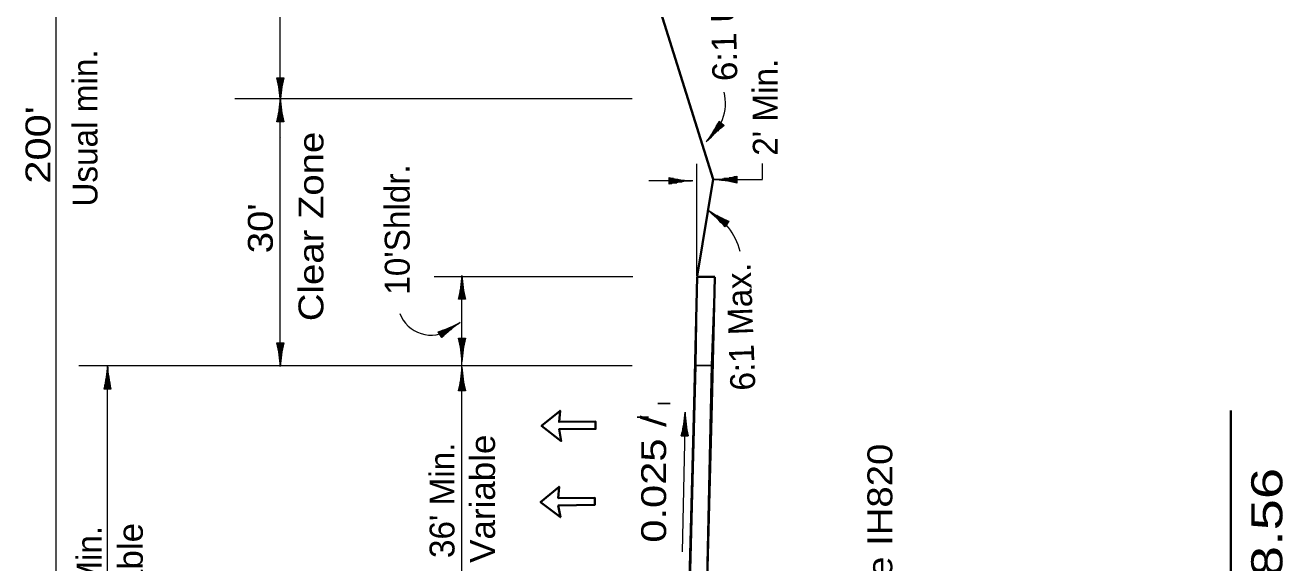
# Model space of a CAD drawing. Extents: x 2363427 to 2368559, y 6957299 to 6980140.
# Drawn here: x 2365718 to 2366425, y 6961583 to 6961886 of the extents above; entities that cross this region are included whole.
import ezdxf
from ezdxf.enums import TextEntityAlignment as Align

# ---------------------------------------------------------------- set-up
doc = ezdxf.new("R2010")
doc.units = 0
doc.header["$LTSCALE"] = 5.6
for name, color, linetype, lineweight in [('3', 7, 'Continuous', 35), ('4', 7, 'Continuous', 13), ('40', 7, 'Continuous', 35), ('8', 7, 'Continuous', 13)]:
    doc.layers.add(name, color=color, linetype=linetype, lineweight=lineweight)

msp = doc.modelspace()

# ---------------------------------------------------------------- linework, layer by layer
at = {"layer": '3'}
for p, q in [((2366007.257, 6962108.215), (2366104.619, 6961799.125)), ((2366095.599, 6961744.603), (2366104.619, 6961799.125)), ((2366105.507, 6961744.281), (2366095.505, 6961744.281)), ((2366103.837, 6961672.617), (2366105.505, 6961744.165)), ((2366100.703, 6961552.723), (2366103.837, 6961672.589))]:
    msp.add_line(p, q, dxfattribs=at)
msp.add_lwpolyline([(2366090.707, 6961552.985), (2366093.839, 6961672.851), (2366095.505, 6961744.281)], dxfattribs=at)
at = {"layer": '3', "lineweight": 13}
for points in [[(2366094.822, 6961694.373), (2366103.663, 6961694.373), (2366105.507, 6961744.281), (2366095.505, 6961744.281)], [(2366087.946, 6961428.343), (2366097.769, 6961428.343), (2366103.663, 6961694.373), (2366094.822, 6961694.373)]]:
    msp.add_lwpolyline(points, close=True, dxfattribs=at)
at = {"layer": '4'}
for p, q in [((2365735.153, 6961372.317), (2365735.153, 6962402.596)), ((2365861.211, 6961823.031), (2365861.298, 6962109.286)), ((2365859.301, 6961856.087), (2365863.131, 6961856.085)), ((2365859.651, 6961856.087), (2365859.651, 6961854.501)), ((2365860.151, 6961856.087), (2365860.149, 6961851.81)), ((2365860.651, 6961856.086), (2365860.649, 6961848.737)), ((2365861.151, 6961856.086), (2365861.147, 6961843.522)), ((2365861.651, 6961856.086), (2365861.649, 6961847.476)), ((2365862.151, 6961856.086), (2365862.149, 6961851.224)), ((2365862.651, 6961856.085), (2365862.649, 6961853.704)), ((2366059.005, 6961844.281), (2365835.607, 6961844.281)), ((2365861.277, 6961831.447), (2365861.277, 6961844.011)), ((2365859.777, 6961831.447), (2365859.777, 6961833.829)), ((2365860.277, 6961831.447), (2365860.277, 6961836.309)), ((2365860.777, 6961831.447), (2365860.777, 6961840.057)), ((2365861.777, 6961831.447), (2365861.777, 6961838.797)), ((2365862.277, 6961831.447), (2365862.277, 6961835.723)), ((2365863.127, 6961831.447), (2365859.297, 6961831.447)), ((2365862.777, 6961831.447), (2365862.777, 6961833.032)), ((2366109.277, 6961830.584), (2366101.259, 6961820.911)), ((2366109.661, 6961830.265), (2366104.167, 6961823.637)), ((2366108.891, 6961830.903), (2366104.201, 6961825.245)), ((2366108.507, 6961831.222), (2366105.777, 6961827.929)), ((2366110.047, 6961829.946), (2366106.943, 6961826.203)), ((2366108.121, 6961831.541), (2366107.11, 6961830.321)), ((2366107.852, 6961831.765), (2366110.801, 6961829.321)), ((2366110.431, 6961829.627), (2366108.911, 6961827.793)), ((2365861.289, 6961822.603), (2365861.211, 6961823.031)), ((2365861.211, 6961694.281), (2365861.211, 6961823.031)), ((2366095.343, 6961744.807), (2366095.343, 6961807.743)), ((2366132.347, 6961799.249), (2366132.347, 6961807.893)), ((2366093.123, 6961798.233), (2366068.419, 6961798.233)), ((2366079.811, 6961796.319), (2366079.811, 6961800.149)), ((2366079.811, 6961799.669), (2366082.193, 6961799.669)), ((2366079.811, 6961799.169), (2366084.673, 6961799.169)), ((2366079.811, 6961798.669), (2366088.421, 6961798.669)), ((2366079.811, 6961798.169), (2366092.375, 6961798.169)), ((2366117.817, 6961798.966), (2366105.253, 6961798.966)), ((2366105.685, 6961798.901), (2366132.263, 6961798.901)), ((2366117.817, 6961798.466), (2366109.207, 6961798.466)), ((2366117.817, 6961799.466), (2366110.467, 6961799.466)), ((2366117.817, 6961799.966), (2366113.541, 6961799.966)), ((2366117.817, 6961800.466), (2366116.231, 6961800.466)), ((2366117.817, 6961800.816), (2366117.817, 6961796.986)), ((2366079.811, 6961797.669), (2366087.161, 6961797.669)), ((2366079.811, 6961797.169), (2366084.087, 6961797.169)), ((2366079.811, 6961796.669), (2366081.395, 6961796.669)), ((2366117.817, 6961797.966), (2366112.955, 6961797.966)), ((2366117.817, 6961797.466), (2366115.435, 6961797.466)), ((2366112.349, 6961774.023), (2366102.109, 6961781.302)), ((2366112.059, 6961773.615), (2366105.043, 6961778.603)), ((2366112.639, 6961774.43), (2366106.649, 6961778.688)), ((2366112.929, 6961774.837), (2366109.443, 6961777.315)), ((2366111.771, 6961773.207), (2366107.807, 6961776.024)), ((2366111.481, 6961772.799), (2366109.539, 6961774.179)), ((2366113.421, 6961775.531), (2366111.203, 6961772.409)), ((2366113.219, 6961775.245), (2366111.927, 6961776.163)), ((2366059.443, 6961744.281), (2365947.725, 6961744.281)), ((2365963.397, 6961731.653), (2365963.397, 6961744.217)), ((2365962.397, 6961731.653), (2365962.397, 6961736.515)), ((2365962.897, 6961731.653), (2365962.897, 6961740.262)), ((2365963.331, 6961685.303), (2365963.331, 6961735.331)), ((2365963.897, 6961731.653), (2365963.897, 6961739.003)), ((2365964.397, 6961731.653), (2365964.397, 6961735.929)), ((2365965.247, 6961731.653), (2365961.417, 6961731.653)), ((2365961.897, 6961731.653), (2365961.897, 6961734.034)), ((2365964.897, 6961731.653), (2365964.897, 6961733.237)), ((2365952.023, 6961710.119), (2365950.035, 6961713.393)), ((2365950.285, 6961712.983), (2365952.321, 6961714.219)), ((2365950.545, 6961712.556), (2365954.701, 6961715.079)), ((2365950.803, 6961712.128), (2365958.163, 6961716.597)), ((2365951.063, 6961711.701), (2365961.803, 6961718.221)), ((2365951.323, 6961711.273), (2365957.605, 6961715.087)), ((2365859.301, 6961707.073), (2365863.131, 6961707.072)), ((2365859.651, 6961707.073), (2365859.651, 6961705.488)), ((2365860.151, 6961707.073), (2365860.149, 6961702.797)), ((2365860.651, 6961707.073), (2365860.649, 6961699.723)), ((2365861.151, 6961707.073), (2365861.147, 6961694.509)), ((2365861.651, 6961707.073), (2365861.649, 6961698.463)), ((2365862.151, 6961707.073), (2365862.149, 6961702.211)), ((2365862.651, 6961707.072), (2365862.649, 6961704.691)), ((2365951.583, 6961710.846), (2365955.239, 6961713.065)), ((2365951.841, 6961710.419), (2365953.197, 6961711.241)), ((2365961.417, 6961709.743), (2365965.247, 6961709.743)), ((2365961.767, 6961709.743), (2365961.767, 6961708.158)), ((2365962.267, 6961709.743), (2365962.267, 6961705.467)), ((2365962.767, 6961709.743), (2365962.767, 6961702.393)), ((2365963.267, 6961709.743), (2365963.267, 6961697.179)), ((2365963.767, 6961709.743), (2365963.767, 6961701.133)), ((2365964.267, 6961709.743), (2365964.267, 6961704.881)), ((2365964.767, 6961709.743), (2365964.767, 6961707.361)), ((2366059.005, 6961694.281), (2365748.007, 6961694.281)), ((2365764.129, 6961433.031), (2365764.129, 6961694.281)), ((2365764.177, 6961681.169), (2365764.177, 6961693.733)), ((2365963.397, 6961680.129), (2365963.397, 6961692.693)), ((2365763.177, 6961681.169), (2365763.177, 6961686.031)), ((2365763.677, 6961681.169), (2365763.677, 6961689.779)), ((2365764.677, 6961681.169), (2365764.677, 6961688.519)), ((2365765.177, 6961681.169), (2365765.177, 6961685.445)), ((2365962.397, 6961680.129), (2365962.397, 6961684.991)), ((2365962.897, 6961680.129), (2365962.897, 6961688.739)), ((2365963.897, 6961680.129), (2365963.897, 6961687.479)), ((2365766.027, 6961681.169), (2365762.197, 6961681.169)), ((2365762.677, 6961681.169), (2365762.677, 6961683.551)), ((2365765.677, 6961681.169), (2365765.677, 6961682.754)), ((2365965.247, 6961680.129), (2365961.417, 6961680.129)), ((2365961.897, 6961680.129), (2365961.897, 6961682.511)), ((2365963.331, 6961551.525), (2365963.331, 6961683.985)), ((2365964.397, 6961680.129), (2365964.397, 6961684.405)), ((2365964.897, 6961680.129), (2365964.897, 6961681.714)), ((2366088.817, 6961668.197), (2366087.205, 6961589.577)), ((2366088.479, 6961654.889), (2366088.737, 6961667.451)), ((2366087.479, 6961654.91), (2366087.567, 6961659.185)), ((2366087.979, 6961654.9), (2366088.129, 6961662.248)), ((2366088.979, 6961654.879), (2366089.155, 6961663.487)), ((2366089.479, 6961654.869), (2366089.579, 6961659.73)), ((2366089.979, 6961654.859), (2366090.027, 6961657.24)), ((2366086.629, 6961654.927), (2366090.459, 6961654.849)), ((2366086.979, 6961654.921), (2366087.011, 6961656.505))]:
    msp.add_line(p, q, dxfattribs=at)
at = {"layer": '4', "lineweight": 25}
for p, q in [((2366073.374, 6961673.067), (2366080.384, 6961673.067)), ((2366068.193, 6961665.452), (2366061.792, 6961665.452))]:
    msp.add_line(p, q, dxfattribs=at)
at = {"layer": '4', "lineweight": 40}
msp.add_line((2366395.533, 6961155.313), (2366395.533, 6961669.131), dxfattribs=at)
at = {"layer": '4'}
for centre, radius, start, end in [((2365789.087, 6961839.214), 72.212, 2.82649, 13.51254), ((2365933.334, 6961839.171), 72.212, 166.45333, 177.13938), ((2366084.429, 6961842.01), 27.012, 306.76831, 13.14994), ((2365789.088, 6961848.341), 72.212, 346.47039, 357.15644), ((2365933.335, 6961848.341), 72.212, 182.84356, 193.52961), ((2366043.018, 6961863.564), 72.212, 323.18777, 333.87382), ((2366154.073, 6961771.509), 72.212, 126.81461, 137.50066), ((2366096.705, 6961870.357), 72.212, 256.47039, 267.15644), ((2366096.705, 6961726.11), 72.212, 92.84356, 103.52961), ((2366100.923, 6961871.025), 72.212, 272.84356, 283.52961), ((2366100.923, 6961726.778), 72.212, 76.47039, 87.15644), ((2366085.672, 6961750.41), 34.94, 13.44028, 63.14536), ((2366056.755, 6961724.973), 72.212, 41.06336, 51.74941), ((2366140.329, 6961842.542), 72.212, 237.43652, 248.12257), ((2365891.208, 6961748.547), 72.212, 346.47039, 357.15644), ((2366035.455, 6961748.547), 72.212, 182.84356, 193.52961), ((2365945.991, 6961730.307), 18.823, 200.84978, 304.56705), ((2365928.044, 6961782.176), 72.212, 287.73061, 298.41666), ((2366002.898, 6961658.871), 72.212, 124.10378, 134.78983), ((2365789.087, 6961690.2), 72.212, 2.82649, 13.51254), ((2365933.334, 6961690.157), 72.212, 166.45333, 177.13938), ((2365891.208, 6961692.85), 72.212, 2.84356, 13.52961), ((2366035.455, 6961692.85), 72.212, 166.47039, 177.15644), ((2365691.988, 6961698.063), 72.212, 346.47039, 357.15644), ((2365836.235, 6961698.063), 72.212, 182.84356, 193.52961), ((2365891.208, 6961697.023), 72.212, 346.47039, 357.15644), ((2366035.455, 6961697.023), 72.212, 182.84356, 193.52961), ((2366016.782, 6961673.257), 72.212, 345.29652, 355.98257), ((2366160.999, 6961670.301), 72.212, 181.66968, 192.35573)]:
    msp.add_arc(centre, radius, start, end, dxfattribs=at)
at = {"layer": '40'}
for p, q in [((2366017.927, 6961662.697), (2366038.433, 6961662.892)), ((2366017.425, 6961619.877), (2366037.931, 6961620.071))]:
    msp.add_line(p, q, dxfattribs=at)
for points in [[(2366017.927, 6961662.697), (2366018.459, 6961669.012), (2366008.073, 6961660.477), (2366019.173, 6961651.875), (2366017.965, 6961658.602)], [(2366017.965, 6961658.602), (2366038.469, 6961658.797), (2366038.433, 6961662.892)], [(2366017.425, 6961619.877), (2366017.957, 6961626.191), (2366007.571, 6961617.657), (2366018.671, 6961609.054), (2366017.463, 6961615.781)], [(2366017.463, 6961615.781), (2366037.967, 6961615.977), (2366037.931, 6961620.071)]]:
    msp.add_lwpolyline(points, dxfattribs=at)
at = {"layer": '8', "lineweight": 40}
for points in [[(2366008.073, 6961660.477), (2366018.459, 6961669.012), (2366017.927, 6961662.697), (2366038.433, 6961662.892), (2366038.469, 6961658.797), (2366017.965, 6961658.602), (2366019.173, 6961651.875)], [(2366007.571, 6961617.657), (2366017.957, 6961626.191), (2366017.425, 6961619.877), (2366037.931, 6961620.071), (2366037.967, 6961615.977), (2366017.463, 6961615.781), (2366018.671, 6961609.054)]]:
    msp.add_lwpolyline(points, close=True, dxfattribs=at)

# ---------------------------------------------------------------- texts
at = {"layer": '3'}
msp.add_text("2' Min.", height=14, rotation=90, dxfattribs=at).set_placement((2366140.821, 6961839.601), align=Align.CENTER)
at = {"layer": '4'}
for s, height, rotation, width, p in [('6:1 Usual', 14, 91.404, 1.05, (2366117.169, 6961895.986)), ("200'", 14, 90, 1.25, (2365732.013, 6961818.406)), ('Clear Zone', 14, 90, 1.15, (2365885.457, 6961772.588)), ("30'", 14, 90, 1.15, (2365857.017, 6961771.542)), ('0.025 /', 14, 90, 1.25, (2366078.099, 6961630.57)), ('Variable', 14, 90, 1.05, (2365981.911, 6961619.499)), ('Profile Grade IH820', 14, 90, 1.15, (2366205.233, 6961555.296)), ('STA 835+60 TO STA 847+98.56', 17.5, 90, 1.35, (2366424.509, 6961407.673)), ('Variable', 14, 90, 1.05, (2365783.941, 6961569.827))]:
    msp.add_text(s, height=height, rotation=rotation, dxfattribs=dict(at, width=width)).set_placement(p, align=Align.CENTER)
for s, rotation, p in [('Usual min.', 90, (2365758.451, 6961827.947)), ("10'Shldr.", 90, (2365933.945, 6961770.86)), ('6:1 Max.', 92.174, (2366126.941, 6961716.407)), ("36' Min.", 90, (2365959.141, 6961618.628)), ("60' Min.", 90, (2365760.735, 6961571.784))]:
    msp.add_text(s, height=14, rotation=rotation, dxfattribs=at).set_placement(p, align=Align.CENTER)

doc.saveas('drawing.dxf')
